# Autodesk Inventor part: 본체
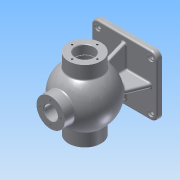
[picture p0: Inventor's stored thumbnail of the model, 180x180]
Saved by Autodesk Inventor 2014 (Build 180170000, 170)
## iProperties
Created: 2017-01
Part Number: 본체
Material: Aluminum 6061
Document SubType Name: Modeling
Designer: ksu
Density: 2.71 g/cm^3
Appearance: Aluminum - Flat
Author: ksu
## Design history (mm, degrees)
sketch "Sketch1"
  geometry: L1 (-62.5, -57.5)-(62.5, -57.5); L2 (62.5, -57.5)-(62.5, 57.5); L3 (62.5, 57.5)-(-62.5, 57.5); L4 (-62.5, 57.5)-(-62.5, -57.5); L5 (-62.5, -57.5)-(62.5, 57.5); L6 (62.5, -57.5)-(-62.5, 57.5); 1 further point
  constraints: 12 end point, 2 midpoint, 2 parallel, 1 horizontal, 1 perpendicular
  dimensions: "d0" = 125 distance of L3.end L2.end; "d1" = 115 distance of L2.end L1.end
extrude "Extrusion1" new body sketch "Sketch1" distance "d2" = 10; taper "d3" = 0 deg
sketch "Sketch2"
  geometry: L1 (-57.5, 0)-(57.5, 0) reference; L2 (-68, 85)-(106.185, 85); L3 (-68, 116)-(-68, 102.5); L4 (68, 116)-(68, 102.5); L5 (-68, 116)-(-42.988, 116); L6 (42.988, 116)-(68, 116); L7 (-68, 102.5)-(-39.278, 102.5); L8 (39.278, 102.5)-(68, 102.5); A1 r 53 centre (0, 85) between (42.988, 116) and (-42.988, 116); A2 r 43 centre (0, 85) between (39.278, 102.5) and (-39.278, 102.5); 1 further point
  constraints: 14 end point, 6 parallel, 4 point on circle, 2 centre point, 1 coincident
  dimensions: "d4" = 106 diameter of A1; "d5" = 86 diameter of A2; "d6" = 85 distance from line of L1 A2.centre; "d9" = 136 distance of L3.start L4.start; "d10" = 68 horizontal distance of point (0, 0) L4.start; "d11" = 136 distance of L3.end L4.end; "d12" = 68 horizontal distance of point (0, 0) L4.end
revolve "Revolution1" sketch "Sketch2" stored, may be unused: angle "d13" = 90 deg
workplane "Work Plane1"
sketch "Sketch3"
  geometry: C1 r 27 at (0, 0); 1 further point
  constraints: 1 centre point, 1 coincident
  dimensions: "d15" = 54 diameter of C1
extrude "Extrusion2" join sketch "Sketch3" distance "d16" = 30; taper "d17" = 0 deg
sketch "Sketch4"
  geometry: C1 r 27 at (0, 0) reference; C2 r 13 at (0, 0)
  constraints: 1 centre point, 1 coincident
  dimensions: "d18" = 26 diameter of C2
extrude "Extrusion3" cut sketch "Sketch4" distance "d19" = 30; taper "d20" = 0 deg
sketch "Sketch5"
  geometry: L1 (62.5, 10)-(-62.5, 10) reference; L2 (-35.008, 53.295)-(-52.5, 10); L3 (35.008, 53.295)-(52.5, 10); L4 (-52.5, 10)-(52.5, 10); L5 (-62.5, 0)-(-62.5, 10) reference; L6 (62.5, 0)-(62.5, 10) reference; A1 r 47.231 centre (0, 85) between (-35.008, 53.295) and (35.008, 53.295); 3 further points
  constraints: 6 end point, 4 point on line, 2 point on circle, 1 centre point, 1 collinear
  dimensions: "d21" = 10 distance of L1.end L2.end; "d22" = 10 distance of L1.start L3.end; "d23" = 22 deg angle of L5 L2; "d24" = 22 deg angle of L6 L3
extrude "Extrusion4" join sketch "Sketch5" stored distance "d25" = 8; taper "d26" = 0 deg
sketch "Sketch6"
  geometry: L1 (57.5, 10)-(-57.5, 10) reference; L2 (-30.87, 51.162)-(-47.5, 10); L3 (30.87, 51.162)-(47.5, 10); L4 (-47.5, 10)-(47.5, 10); L5 (-57.5, 0)-(-57.5, 10) reference; L6 (57.5, 0)-(57.5, 10) reference; A1 r 45.804 centre (0, 85) between (-30.87, 51.162) and (30.87, 51.162); 1 further point
  constraints: 6 end point, 2 point on circle, 2 point on line, 1 centre point, 1 collinear
  dimensions: "d27" = 10 distance of L1.end L2.end; "d28" = 10 distance of L1.start L3.end; "d29" = 22 deg angle of L5 L2; "d30" = 22 deg angle of L6 L3
extrude "Extrusion5" join sketch "Sketch6" stored distance "d31" = 8; taper "d32" = 0 deg
fillet "Fillet1" dims "d33" = 12
sketch "Sketch7"
  geometry: A1 r 12 centre (-50.5, 45.5) between (-50.5, 57.5) and (-62.5, 45.5) reference; A2 r 12 centre (-50.5, -45.5) between (-62.5, -45.5) and (-50.5, -57.5) reference; A3 r 12 centre (50.5, -45.5) between (50.5, -57.5) and (62.5, -45.5) reference; A4 r 12 centre (50.5, 45.5) between (62.5, 45.5) and (50.5, 57.5) reference; 5 further points
  constraints: 4 coincident
hole "Hole1" sketch "Sketch7" at (-50.5, 45.5), (50.5, 45.5), (50.5, -45.5), (-50.5, -45.5) diameter "d34" = 8; stored, may be unused: countersink angle "d38" = 90 deg, drill point angle "d40" = 118 deg; dims "d35" = 6, "d36" = 12, "d37" = 3, "d39" = 10
sketch "Sketch8" dims "d41" = 45
  geometry: C1 r 31 at (0, 0) reference; 3 further points
  constraints: 1 coincident, 1 vertical alignment, 2 other
hole "Hole2" sketch "Sketch8" at (0, 22.5) diameter "d42" = 3.459; stored, may be unused: countersink angle "d46" = 90 deg, drill point angle "d48" = 118 deg; dims "d43" = 12, "d44" = 12, "d45" = 3, "d47" = 15
workaxis "Work Axis1"
pattern_circular "Circular Pattern1" dims angle "d50" = 360 deg
sketch "Sketch9" dims "d52" = 48
  geometry: C1 r 17.5 at (0, 0) reference; 3 further points
  constraints: 1 coincident, 1 vertical alignment, 2 other
hole "Hole3" sketch "Sketch9" at (0, 24) diameter "d53" = 3.459; stored, may be unused: countersink angle "d57" = 90 deg, drill point angle "d59" = 118 deg; dims "d54" = 16, "d55" = 12, "d56" = 3, "d58" = 19
pattern_circular "Circular Pattern2" dims angle "d61" = 360 deg
workplane "Work Plane2"
sketch "Sketch10"
  geometry: L1 (142.729, 66.239)-(142.729, 24.761); L2 (142.729, 24.761)-(137.271, 24.761); L3 (137.271, 24.761)-(137.271, 66.239); L4 (137.271, 66.239)-(142.729, 66.239); L5 (140, 66.239)-(140, 24.761); L6 (142.729, 45.5)-(137.271, 45.5); L7 (150, 72.5)-(130.607, 72.5) reference; 1 further point
  constraints: 4 end point, 4 midpoint, 2 other
  dimensions: "d64" = 27 distance from line of L7.start L6; "d65" = 10 distance from line of L7.start L5
emboss "Emboss1" sketch "Sketch10" dims "d0" = 125, "d1" = 115, "d66" = 0.5, "d67" = 0
sketch "Sketch11"
  geometry: L1 (-27.094, 118.39)-(-27.094, 85); L2 (-27.094, 85)-(31.416, 85); L3 (31.416, 85)-(31.543, 114.224); L4 (-95.2, 85)-(95.2, 85) reference; A1 r 43 centre (0, 85) between (-24.98, 120) and (24.98, 120) reference; A2 r 43 centre (0, 85) between (31.543, 114.224) and (-27.094, 118.39); 1 further point
  constraints: 6 end point, 4 point on circle, 1 centre point, 1 coincident, 1 concentric, 1 perpendicular, 1 vertical
revolve "Revolution2" sketch "Sketch11" stored, may be unused: angle "d68" = 90 deg
chamfer "Chamfer1" distance "d69" = 1; stored, may be unused: second distance "d70" = 2, angle "d71" = 45 deg
sketch "Sketch12"
  geometry: L1 (50.25, 103.5)-(52, 103.5); L2 (52, 103.5)-(52, 85); L3 (52, 85)-(50.25, 85); L4 (50.25, 85)-(50.25, 103.5); L5 (45.5, 0)-(-45.5, 0) reference; L6 (68, 66.5)-(68, 103.5) reference; L7 (-95.2, 85)-(95.2, 85) reference; 1 further point
  constraints: 8 end point, 2 parallel, 1 horizontal, 1 perpendicular
  dimensions: "d72" = 85 distance between parallel lines of L5 L3; "d73" = 1.75 distance of L1.start L1.end; "d74" = 16 distance between parallel lines of L6 L2; "d76" = 18.5 distance between parallel lines of L3 L1
revolve "Revolution3" sketch "Sketch12" stored, may be unused: angle "d75" = 90 deg
sketch "Sketch13" dims "d77" = 40
  geometry: C1 r 27 at (0, 0) reference; 2 further points
  constraints: 1 coincident, 1 vertical alignment, 2 other
hole "Hole4" sketch "Sketch13" at (0, 20) diameter "d78" = 3.459; stored, may be unused: countersink angle "d82" = 90 deg, drill point angle "d84" = 118 deg; dims "d79" = 9, "d80" = 12, "d81" = 3, "d83" = 11
workaxis "Work Axis2"
pattern_circular "Circular Pattern3" dims angle "d86" = 360 deg
fillet "Fillet2" dims "d88" = 3
fillet "Fillet3" dims "d89" = 3
fillet "Fillet4" dims "d90" = 3
fillet "Fillet5" dims "d91" = 3
fillet "Fillet6" dims "d92" = 3
fillet "Fillet7" dims "d93" = 3
chamfer "Chamfer2" distance "d94" = 1; stored, may be unused: second distance "d95" = 2, angle "d96" = 45 deg
body "Solid1"
other parameters: "d7" = 62, "d8" = 35
